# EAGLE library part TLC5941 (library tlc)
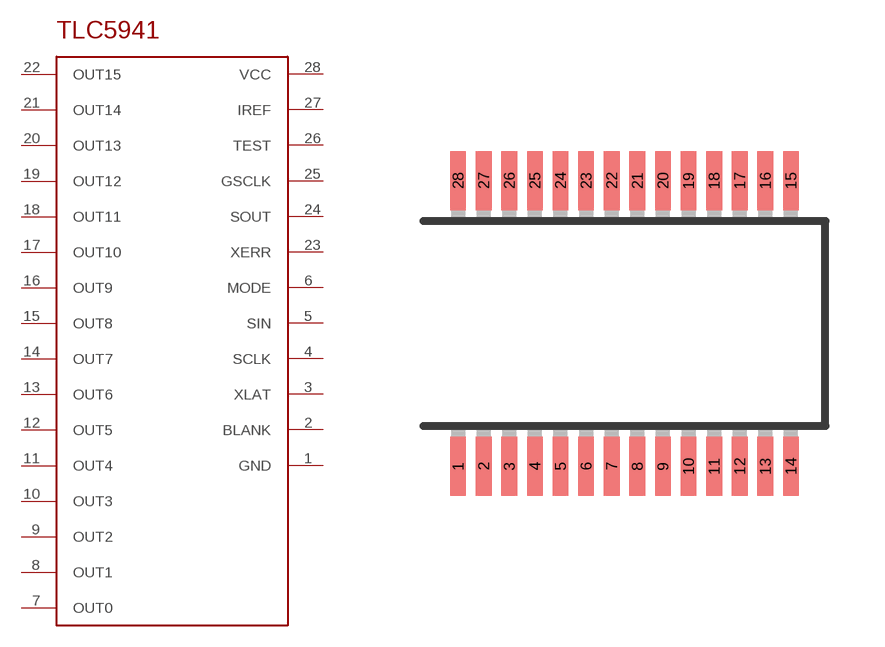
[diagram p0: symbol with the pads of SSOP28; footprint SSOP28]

Designator prefix -

## TLC5941  [SSOP28]
1  GND
2  BLANK
3  XLAT
4  SCLK
5  SIN
6  MODE
7  OUT0
8  OUT1
9  OUT2
10  OUT3
11  OUT4
12  OUT5
13  OUT6
14  OUT7
15  OUT8
16  OUT9
17  OUT10
18  OUT11
19  OUT12
20  OUT13
21  OUT14
22  OUT15
23  XERR
24  SOUT
25  GSCLK
26  TEST
27  IREF
28  VCC

## Footprint SSOP28 (pad centres in mm)
Shrink Small Outline Package package type SS
smd 0.4 x 1.5: 1 -4.225,-3.625; 2 -3.575,-3.625; 3 -2.925,-3.625; 4 -2.275,-3.625; 5 -1.625,-3.625; 6 -0.975,-3.625; 7 -0.325,-3.625; 8 0.325,-3.625; 9 0.975,-3.625; 10 1.625,-3.625; 11 2.275,-3.625; 12 2.925,-3.625; 13 3.575,-3.625; 14 4.225,-3.625; 15 4.225,3.625; 16 3.575,3.625; 17 2.925,3.625; 18 2.275,3.625; 19 1.625,3.625; 20 0.975,3.625; 21 0.325,3.625; 22 -0.325,3.625; 23 -0.975,3.625; 24 -1.625,3.625; 25 -2.275,3.625; 26 -2.925,3.625; 27 -3.575,3.625; 28 -4.225,3.625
